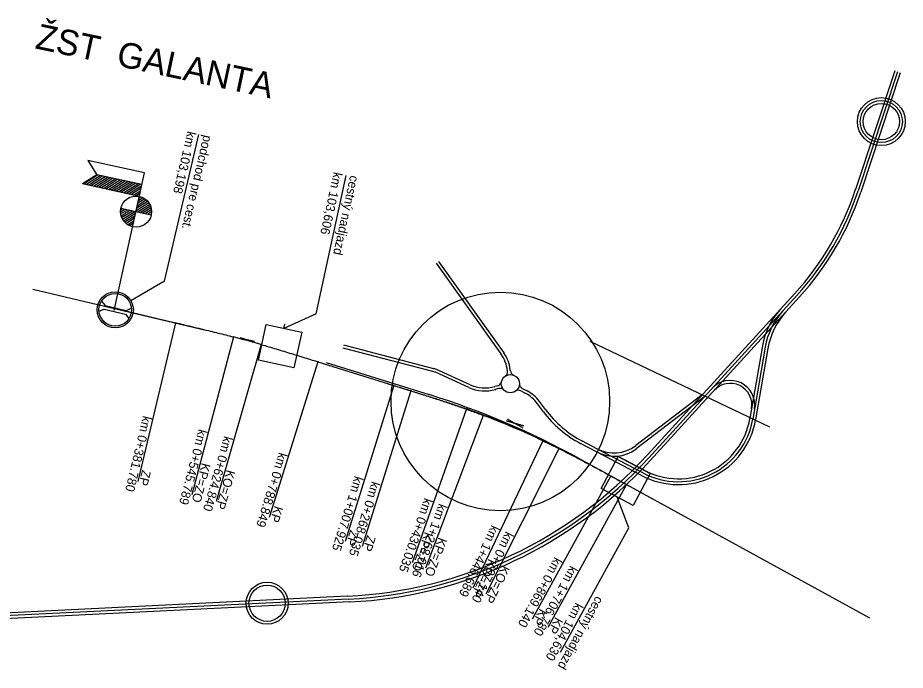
# Model space of a CAD drawing. Extents: x -566241 to -446826, y -1330151 to -1274078.
# Drawn here: x -528029 to -525582, y -1281724 to -1279926 of the extents above; entities that cross this region are included whole.
import ezdxf

# ---------------------------------------------------------------- set-up
doc = ezdxf.new("R2010")
doc.units = 0
for name, color, linetype in [('1-POPIS', 7, 'Continuous'), ('10_cesty_plochy', 7, 'Continuous'), ('os', 7, 'Continuous'), ('os hl bod', 7, 'Continuous'), ('Posúdenie 200km Bloss', 7, 'Continuous'), ('Posúdenie_200km', 7, 'Continuous'), ('sit_stanicenie', 7, 'Continuous'), ('STANICE', 7, 'Continuous'), ('stanicenie', 7, 'Continuous')]:
    doc.layers.add(name, color=color, linetype=linetype)

msp = doc.modelspace()

# ---------------------------------------------------------------- linework, layer by layer
at = {"layer": '1-POPIS'}
for p, q in [((-527624.7, -1280652), (-527530, -1280247.6)), ((-527206.8, -1280742.2), (-527123.8, -1280360.7)), ((-527624.7, -1280652), (-527717.3, -1280705.9)), ((-527798.4, -1280706.8), (-527788.5, -1280719.4)), ((-527790.8, -1280729.1), (-527805.2, -1280736)), ((-527790.8, -1280729.1), (-527732.4, -1280742.8)), ((-527788.5, -1280719.4), (-527730.1, -1280733.1)), ((-527730.1, -1280733.1), (-527715.7, -1280726.2)), ((-527732.4, -1280742.8), (-527722.6, -1280755.4)), ((-527206.8, -1280742.2), (-527295.2, -1280782.3)), ((-527295.2, -1280782.3), (-527292.7, -1280770.8)), ((-526344.7, -1281332.4), (-526376.8, -1281247)), ((-526532.6, -1281674.7), (-526344.7, -1281332.4))]:
    msp.add_line(p, q, dxfattribs=at)
for points in [[(-527344, -1280771.7), (-527246.3, -1280793), (-527267.6, -1280890.7), (-527365.3, -1280869.4)], [(-526373.7, -1281135.2), (-526285.5, -1281182.5), (-526332.8, -1281270.6), (-526420.9, -1281223.4)]]:
    msp.add_lwpolyline(points, close=True, dxfattribs=at)
for radius in [50, 45]:
    msp.add_circle((-527760.5, -1280731.1), radius, dxfattribs=at)
at = {"layer": '10_cesty_plochy'}
for p, q in [((-525611.3, -1280072.7), (-525719.1, -1280399)), ((-525603.7, -1280075.2), (-525712.1, -1280403.1)), ((-525596.1, -1280077.8), (-525705, -1280407.2)), ((-526875.2, -1280602.6), (-526697, -1280852.2)), ((-526868.7, -1280598), (-526689.3, -1280849.3)), ((-527988.1, -1280673.9), (-527510.4, -1280787)), ((-526293.3, -1281131.2), (-525887.9, -1280687.3)), ((-526289.6, -1281139), (-525880.9, -1280691.5)), ((-526285.9, -1281146.8), (-525873.8, -1280695.6)), ((-527133.2, -1280835.7), (-526885.6, -1280900.5)), ((-527131.2, -1280828), (-526882.9, -1280893)), ((-526452.2, -1280817.4), (-525956, -1281053.7)), ((-525975.9, -1280830.5), (-526010.4, -1281030.8)), ((-525968.4, -1280834.1), (-526002.5, -1281032.2)), ((-525960.9, -1280837.8), (-525994.6, -1281033.5)), ((-527179.2, -1280876.1), (-526950.9, -1280947.3)), ((-527179.2, -1280876.1), (-526895.2, -1280964.7)), ((-526785.5, -1280944.9), (-526877.7, -1280903.3)), ((-526782.2, -1280937.7), (-526875, -1280895.8)), ((-526679, -1280900.1), (-526679.1, -1280899.1)), ((-526671, -1280899.2), (-526671.4, -1280896.1)), ((-526703.8, -1280948.2), (-526713.8, -1280951)), ((-526706, -1280940.5), (-526713.6, -1280942.7)), ((-526641.7, -1280954.6), (-526629.9, -1280960.8)), ((-526638, -1280947.5), (-526624.6, -1280954.6)), ((-526574.5, -1281005.6), (-526590.8, -1280983.6)), ((-526142.5, -1280965.4), (-526325, -1281104.9)), ((-526137.6, -1280971.8), (-526324.2, -1281114.4)), ((-526579.8, -1281011.9), (-526596.1, -1280989.8)), ((-526431.3, -1281123.5), (-526477.8, -1281099.2)), ((-526432.1, -1281114.1), (-526472.5, -1281092.9)), ((-526304, -1281181.2), (-526432.1, -1281114.1)), ((-526307.7, -1281188.3), (-526431.3, -1281123.5)), ((-526482.7, -1281140.2), (-525681.1, -1281580.3)), ((-526300.3, -1281174.1), (-526375.8, -1281134.5)), ((-527120.7, -1281520.5), (-528089.6, -1281568)), ((-527113.3, -1281536.2), (-528094.5, -1281584.2)), ((-527117, -1281528.3), (-528092, -1281576.1))]:
    msp.add_line(p, q, dxfattribs=at)
for centre, radius in [((-525648.1, -1280212.3), 66), ((-525648.1, -1280212.3), 58), ((-525648.1, -1280212.3), 50), ((-526698.6, -1280983.6), 301.3), ((-526671, -1280934.7), 25), ((-527341.7, -1281539.9), 58), ((-527341.7, -1281539.9), 50)]:
    msp.add_circle(centre, radius, dxfattribs=at)
for centre, radius, start, end in [((-526478.7, -1280147.8), 800, 317.5966, 341.7049), ((-526471.6, -1280152), 800, 317.5966, 341.7049), ((-526464.6, -1280156.1), 800, 317.5966, 341.7049), ((-525778.8, -1280864.4), 200, 137.5966, 170.2357), ((-525771.3, -1280868.1), 200, 137.5966, 170.2357), ((-525763.8, -1280871.7), 200, 137.5966, 170.2357), ((-526778.4, -1280910.3), 100, 6.4527, 35.5191), ((-526770.7, -1280907.4), 100, 6.4527, 35.5191), ((-526898.3, -1280948.9), 50, 65.7033, 75.323), ((-526895.6, -1280941.3), 50, 65.7033, 75.323), ((-526693.9, -1280901.8), 15, 304.812, 6.4527), ((-526656.1, -1280897.5), 15, 186.4527, 248.0933), ((-526710.1, -1280926.1), 15, 285.9428, 347.5834), ((-526631, -1280934.2), 15, 180.5894, 242.23), ((-526064.9, -1280993.8), 68, 350.2357, 137.5966), ((-526064.9, -1280993.8), 60, 350.2357, 137.5966), ((-526741.1, -1280846.5), 108, 245.7033, 285.9428), ((-526741.1, -1280846.5), 100, 245.7033, 285.9428), ((-526699.7, -1280962.6), 15, 44.3021, 105.9428), ((-526648.7, -1280967.9), 15, 62.23, 123.8707), ((-526671.2, -1281043.1), 100, 36.5095, 62.23), ((-527565.5, -1283112.6), 2250, 61.2335, 72.6695), ((-526676.5, -1281049.3), 100, 36.5095, 62.23), ((-526333.3, -1280827.1), 300, 216.5095, 242.3626), ((-526338.7, -1280833.4), 300, 216.5095, 242.3626), ((-526207.5, -1280996.9), 216, 242.3626, 350.2357), ((-526207.5, -1280996.9), 208, 242.3626, 350.2357), ((-526207.5, -1280996.9), 200, 242.3626, 350.2357), ((-526385.7, -1281025.5), 100, 242.3626, 307.4004), ((-527179.4, -1280321.9), 1200, 272.8042, 317.5966), ((-526384.9, -1281034.9), 100, 242.3626, 307.4004), ((-527175.7, -1280329.8), 1200, 272.8042, 317.5966), ((-527172, -1280337.6), 1200, 272.8042, 317.5966)]:
    msp.add_arc(centre, radius, start, end, dxfattribs=at)
at = {"layer": 'os'}
for p, q in [((-527010.6, -1280933.9), (-526945.7, -1280954.2)), ((-526393.9, -1281189), (-526279.2, -1281251.9))]:
    msp.add_line(p, q, dxfattribs=at)
for points in [[(-526945.7, -1280954.2), (-526941.6, -1280955.5), (-526937.6, -1280956.7), (-526933.5, -1280958), (-526929.4, -1280959.3), (-526925.3, -1280960.5), (-526921.3, -1280961.8), (-526917.2, -1280963.1), (-526913.1, -1280964.4), (-526909.1, -1280965.6), (-526905, -1280966.9), (-526900.9, -1280968.2), (-526896.9, -1280969.5), (-526892.8, -1280970.7), (-526888.7, -1280972), (-526884.7, -1280973.3), (-526880.6, -1280974.6), (-526876.5, -1280975.9), (-526872.5, -1280977.2), (-526868.4, -1280978.5), (-526864.4, -1280979.8), (-526860.3, -1280981.1), (-526856.2, -1280982.4), (-526852.2, -1280983.7), (-526848.1, -1280985), (-526844.1, -1280986.3), (-526840, -1280987.7), (-526836, -1280989), (-526831.9, -1280990.3), (-526827.9, -1280991.7), (-526823.8, -1280993), (-526819.8, -1280994.4), (-526815.8, -1280995.8), (-526811.7, -1280997.2), (-526807.7, -1280998.5), (-526803.7, -1280999.9), (-526799.6, -1281001.3), (-526795.6, -1281002.7), (-526791.6, -1281004.2)], [(-526536.8, -1281112.6), (-526533, -1281114.5), (-526529.2, -1281116.4), (-526525.4, -1281118.3), (-526521.6, -1281120.3), (-526517.8, -1281122.2), (-526514, -1281124.2), (-526510.2, -1281126.1), (-526506.4, -1281128.1), (-526502.6, -1281130.1), (-526498.9, -1281132.1), (-526495.1, -1281134), (-526491.3, -1281136), (-526487.6, -1281138), (-526483.8, -1281140), (-526480, -1281142), (-526476.3, -1281144), (-526472.5, -1281146.1), (-526468.8, -1281148.1), (-526465, -1281150.1), (-526461.3, -1281152.1), (-526457.5, -1281154.2), (-526453.8, -1281156.2), (-526450, -1281158.2), (-526446.3, -1281160.3), (-526442.5, -1281162.3), (-526438.8, -1281164.4), (-526435.1, -1281166.4), (-526431.3, -1281168.5), (-526427.6, -1281170.5), (-526423.8, -1281172.5), (-526420.1, -1281174.6), (-526416.4, -1281176.6), (-526412.6, -1281178.7), (-526408.9, -1281180.7), (-526405.1, -1281182.8), (-526401.4, -1281184.9), (-526397.7, -1281186.9), (-526393.9, -1281189)]]:
    msp.add_lwpolyline(points, dxfattribs=at)
msp.add_arc((-527523.8, -1283078.7), 2200, 63.343, 70.5598, dxfattribs=at)
at = {"layer": 'os hl bod'}
for centre in [(-526945.7, -1280954.2), (-526791.6, -1281004.2), (-526536.8, -1281112.6), (-526393.9, -1281189)]:
    msp.add_circle(centre, 0.75, dxfattribs=at)
at = {"layer": 'Posúdenie 200km Bloss'}
for p, q in [((-526680, -1281031.9), (-526636.2, -1281055.9)), ((-526634.7, -1281051.2), (-526681.6, -1281036.6))]:
    msp.add_line(p, q, dxfattribs=at)
at = {"layer": 'Posúdenie_200km'}
for p, q in [((-527762.1, -1280726.8), (-527594, -1280766.7)), ((-527376.7, -1280818.3), (-527416.1, -1280808.9)), ((-527415.6, -1280807.6), (-527377.1, -1280819.6)), ((-527201.6, -1280874.4), (-526992.4, -1280939.6)), ((-526680, -1281031.9), (-526636.2, -1281055.9)), ((-526681.6, -1281036.6), (-526634.7, -1281051.2)), ((-526351, -1281212.5), (-526181.5, -1281305.5))]:
    msp.add_line(p, q, dxfattribs=at)
for points in [[(-527673.6, -1280747.8), (-527673.8, -1280748.8)], [(-527594, -1280766.7), (-527697.9, -1281204.5)], [(-527594, -1280766.7), (-527588.7, -1280768), (-527583.4, -1280769.2), (-527578, -1280770.5), (-527572.7, -1280771.7), (-527567.4, -1280773), (-527562.1, -1280774.3), (-527556.8, -1280775.5), (-527551.5, -1280776.8), (-527546.1, -1280778.1), (-527540.8, -1280779.4), (-527535.5, -1280780.6), (-527530.2, -1280781.9), (-527524.9, -1280783.2), (-527519.6, -1280784.5), (-527514.3, -1280785.8), (-527508.9, -1280787.1), (-527503.6, -1280788.4), (-527498.3, -1280789.7), (-527493, -1280791), (-527487.7, -1280792.3), (-527482.4, -1280793.6), (-527477.1, -1280795), (-527471.8, -1280796.3), (-527466.5, -1280797.6), (-527461.2, -1280799), (-527455.9, -1280800.3), (-527450.6, -1280801.7), (-527445.3, -1280803), (-527440, -1280804.4), (-527434.7, -1280805.8)], [(-527576.3, -1280770.9), (-527576.5, -1280771.9)], [(-527434.7, -1280805.8), (-527548.9, -1281241.1)], [(-527479.1, -1280794.5), (-527479.3, -1280795.4)], [(-527358.5, -1280826.7), (-527482.4, -1281259.3)], [(-527382.4, -1280820), (-527382.7, -1280820.9)], [(-527358.5, -1280826.7), (-527353.2, -1280828.2), (-527348, -1280829.7), (-527342.7, -1280831.3), (-527337.5, -1280832.8), (-527332.2, -1280834.3), (-527327, -1280835.9), (-527321.8, -1280837.4), (-527316.5, -1280839), (-527311.3, -1280840.6), (-527306, -1280842.1), (-527300.8, -1280843.7), (-527295.6, -1280845.3), (-527290.3, -1280846.9), (-527285.1, -1280848.5), (-527279.9, -1280850.1), (-527274.7, -1280851.7), (-527269.4, -1280853.3), (-527264.2, -1280854.9), (-527259, -1280856.5), (-527253.8, -1280858.1), (-527248.5, -1280859.7), (-527243.3, -1280861.3), (-527238.1, -1280863), (-527232.9, -1280864.6), (-527227.7, -1280866.2), (-527222.4, -1280867.8), (-527217.2, -1280869.5), (-527212, -1280871.1), (-527206.8, -1280872.7), (-527201.6, -1280874.4)], [(-527286.4, -1280848.1), (-527286.7, -1280849)], [(-527201.6, -1280874.4), (-527335.6, -1281303.9)], [(-527190.9, -1280877.7), (-527191.2, -1280878.6)], [(-527095.5, -1280907.5), (-527095.8, -1280908.4)], [(-526992.4, -1280939.6), (-527126.5, -1281369.2)], [(-527000, -1280937.2), (-527000.3, -1280938.2)], [(-526992.4, -1280939.6), (-526988.4, -1280940.9), (-526984.3, -1280942.2), (-526980.2, -1280943.4), (-526976.2, -1280944.7), (-526972.1, -1280946), (-526968, -1280947.2), (-526963.9, -1280948.5), (-526959.9, -1280949.8), (-526955.8, -1280951.1), (-526951.7, -1280952.3), (-526947.7, -1280953.6), (-526943.6, -1280954.9), (-526939.5, -1280956.2), (-526935.5, -1280957.5), (-526931.4, -1280958.7), (-526927.3, -1280960), (-526923.3, -1280961.3), (-526919.2, -1280962.6), (-526915.1, -1280963.9), (-526911.1, -1280965.2), (-526907, -1280966.5), (-526903, -1280967.8), (-526898.9, -1280969.1), (-526894.8, -1280970.4), (-526890.8, -1280971.7), (-526886.7, -1280973), (-526882.7, -1280974.3), (-526878.6, -1280975.6), (-526874.6, -1280977), (-526870.5, -1280978.3), (-526866.5, -1280979.6), (-526862.4, -1280981), (-526858.4, -1280982.3), (-526854.3, -1280983.6), (-526850.3, -1280985), (-526846.2, -1280986.3), (-526842.2, -1280987.7), (-526838.1, -1280989.1), (-526834.1, -1280990.4), (-526830.1, -1280991.8), (-526826, -1280993.2), (-526822, -1280994.6), (-526818, -1280995.9), (-526813.9, -1280997.3), (-526809.9, -1280998.7), (-526805.9, -1281000.1), (-526801.9, -1281001.5), (-526797.8, -1281003), (-526793.8, -1281004.4), (-526789.8, -1281005.8), (-526785.8, -1281007.2), (-526781.8, -1281008.7), (-526777.8, -1281010.1), (-526773.7, -1281011.6), (-526769.7, -1281013), (-526765.7, -1281014.5), (-526761.7, -1281016), (-526757.7, -1281017.5), (-526753.7, -1281019), (-526749.8, -1281020.5), (-526745.8, -1281022)], [(-526904.6, -1280967.3), (-526904.9, -1280968.2)], [(-526809.7, -1280998.8), (-526810, -1280999.7)], [(-526745.8, -1281022), (-526905, -1281442.9)], [(-526715.9, -1281033.5), (-526716.3, -1281034.4)], [(-526623.8, -1281072.3), (-526624.2, -1281073.2)], [(-526581.4, -1281091.9), (-526774.2, -1281498.5)], [(-526581.4, -1281091.9), (-526577.5, -1281093.7), (-526573.7, -1281095.5), (-526569.9, -1281097.4), (-526566, -1281099.2), (-526562.2, -1281101.1), (-526558.3, -1281103), (-526554.5, -1281104.8), (-526550.7, -1281106.7), (-526546.9, -1281108.6), (-526543, -1281110.5), (-526539.2, -1281112.4), (-526535.4, -1281114.3), (-526531.6, -1281116.2), (-526527.8, -1281118.1), (-526524, -1281120.1), (-526520.2, -1281122), (-526516.4, -1281123.9), (-526512.6, -1281125.8), (-526508.8, -1281127.8), (-526505, -1281129.7), (-526501.2, -1281131.7), (-526497.4, -1281133.7), (-526493.6, -1281135.6), (-526489.8, -1281137.6), (-526486.1, -1281139.6), (-526482.3, -1281141.5), (-526478.5, -1281143.5), (-526474.7, -1281145.5), (-526471, -1281147.5), (-526467.2, -1281149.5), (-526463.4, -1281151.5), (-526459.7, -1281153.5), (-526455.9, -1281155.5), (-526452.1, -1281157.5), (-526448.4, -1281159.5), (-526444.6, -1281161.5), (-526440.9, -1281163.5), (-526437.1, -1281165.5), (-526433.3, -1281167.6), (-526429.6, -1281169.6), (-526425.8, -1281171.6), (-526422.1, -1281173.6), (-526418.3, -1281175.7), (-526414.6, -1281177.7), (-526410.8, -1281179.7), (-526407.1, -1281181.8), (-526403.4, -1281183.8), (-526399.6, -1281185.9), (-526395.9, -1281187.9), (-526392.1, -1281189.9), (-526388.4, -1281192), (-526384.6, -1281194), (-526380.9, -1281196.1), (-526377.2, -1281198.1), (-526373.4, -1281200.2), (-526369.7, -1281202.2), (-526365.9, -1281204.3), (-526362.2, -1281206.3), (-526358.5, -1281208.4), (-526354.7, -1281210.4), (-526351, -1281212.5)], [(-526533.5, -1281115.3), (-526533.9, -1281116.2)], [(-526444.8, -1281161.4), (-526445.2, -1281162.3)], [(-526351, -1281212.5), (-526567.5, -1281607)], [(-526356.9, -1281209.2), (-526357.4, -1281210.1)], [(-526269.3, -1281257.3), (-526269.8, -1281258.2)], [(-526181.6, -1281305.4), (-526182.1, -1281306.3)]]:
    msp.add_lwpolyline(points, dxfattribs=at)
for centre in [(-527594, -1280766.7), (-527434.7, -1280805.8), (-527358.5, -1280826.7), (-527201.6, -1280874.4), (-526992.4, -1280939.6), (-526745.8, -1281022), (-526581.4, -1281091.9), (-526351, -1281212.5)]:
    msp.add_circle(centre, 0.75, dxfattribs=at)
for centre, radius, start, end in [((-528322.5, -1284191.3), 3500, 74.0118, 75.3059), ((-527524.1, -1283079.7), 2200, 64.6284, 69.2817)]:
    msp.add_arc(centre, radius, start, end, dxfattribs=at)
at = {"layer": 'sit_stanicenie'}
for points in [[(-527010.6, -1280933.9), (-527010.9, -1280934.9)], [(-526915.2, -1280963.7), (-526915.5, -1280964.7)], [(-526820, -1280994.3), (-526820.3, -1280995.3)], [(-526726, -1281028.5), (-526726.4, -1281029.4)], [(-526633.7, -1281066.9), (-526634.1, -1281067.8)], [(-526543.2, -1281109.4), (-526543.6, -1281110.3)], [(-526454.6, -1281155.8), (-526455.1, -1281156.6)], [(-526366.9, -1281203.8), (-526367.4, -1281204.7)], [(-526279.2, -1281251.9), (-526279.7, -1281252.8)]]:
    msp.add_lwpolyline(points, dxfattribs=at)
at = {"layer": 'STANICE'}
for p, q in [((-527836.5, -1280319.2), (-527811.4, -1280358.6)), ((-527679.6, -1280353.9), (-527836.5, -1280319.2)), ((-527811.4, -1280358.6), (-527850.7, -1280383.7)), ((-527848.4, -1280384.2), (-527809, -1280359.1)), ((-527841.5, -1280385.7), (-527802.1, -1280360.6)), ((-527834.6, -1280387.2), (-527795.2, -1280362.1)), ((-527827.7, -1280388.8), (-527788.3, -1280363.7)), ((-527820.8, -1280390.3), (-527781.4, -1280365.2)), ((-527813.9, -1280391.8), (-527774.5, -1280366.7)), ((-527686.7, -1280386.1), (-527811.4, -1280358.6)), ((-527806.9, -1280393.4), (-527767.6, -1280368.2)), ((-527800, -1280394.9), (-527760.7, -1280369.8)), ((-527793.1, -1280396.4), (-527753.8, -1280371.3)), ((-527786.2, -1280397.9), (-527746.9, -1280372.8)), ((-527763.5, -1280733.2), (-527679.6, -1280353.9)), ((-527693.8, -1280418.4), (-527850.7, -1280383.7)), ((-527779.3, -1280399.5), (-527740, -1280374.4)), ((-527772.4, -1280401), (-527733.1, -1280375.9)), ((-527765.5, -1280402.5), (-527726.2, -1280377.4)), ((-527758.6, -1280404), (-527719.3, -1280378.9)), ((-527751.7, -1280405.6), (-527712.3, -1280380.5)), ((-527744.8, -1280407.1), (-527705.4, -1280382)), ((-527737.9, -1280408.6), (-527698.5, -1280383.5)), ((-527731, -1280410.2), (-527691.6, -1280385)), ((-527724.1, -1280411.7), (-527687.2, -1280388.1)), ((-527717.2, -1280413.2), (-527688.7, -1280395)), ((-527710.3, -1280414.7), (-527690.2, -1280401.9)), ((-527710.3, -1280414.7), (-527690.2, -1280401.9)), ((-527703.4, -1280416.3), (-527691.7, -1280408.8)), ((-527703.4, -1280416.3), (-527691.7, -1280408.8)), ((-527696.5, -1280417.8), (-527693.3, -1280415.7)), ((-527696.5, -1280417.8), (-527693.3, -1280415.7)), ((-527696.3, -1280429.5), (-527684.1, -1280421.8)), ((-527694.8, -1280422.6), (-527689.8, -1280419.5)), ((-527702.4, -1280457.2), (-527668.2, -1280435.3)), ((-527700.9, -1280450.3), (-527671.3, -1280431.4)), ((-527699.4, -1280443.4), (-527675, -1280427.8)), ((-527699.4, -1280461.2), (-527665.5, -1280439.5)), ((-527697.8, -1280436.4), (-527679.3, -1280424.6)), ((-527692.5, -1280462.7), (-527663.3, -1280444.1)), ((-527746.1, -1280461.3), (-527734, -1280453.6)), ((-527745.8, -1280455.2), (-527740.9, -1280452)), ((-527745.7, -1280466.9), (-527727.1, -1280455.1)), ((-527745.1, -1280451.1), (-527661.1, -1280469.7)), ((-527744.5, -1280472.1), (-527720.2, -1280456.6)), ((-527742.8, -1280477), (-527713.3, -1280458.1)), ((-527740.6, -1280481.5), (-527706.4, -1280459.7)), ((-527737.9, -1280485.7), (-527704, -1280464.1)), ((-527734.7, -1280489.6), (-527705.5, -1280471)), ((-527685.6, -1280464.2), (-527661.7, -1280449)), ((-527678.7, -1280465.8), (-527660.6, -1280454.2)), ((-527671.8, -1280467.3), (-527660.1, -1280459.8)), ((-527731, -1280493.2), (-527707, -1280477.9)), ((-527726.7, -1280496.4), (-527708.5, -1280484.8)), ((-527721.8, -1280499.1), (-527710.1, -1280491.7))]:
    msp.add_line(p, q, dxfattribs=at)
msp.add_circle((-527703.1, -1280460.4), 43, dxfattribs=at)
at = {"layer": 'stanicenie'}
for points in [[(-526945.7, -1280954.2), (-527079.7, -1281383.8)], [(-526791.6, -1281004.2), (-526941.4, -1281428.5)], [(-526536.8, -1281112.6), (-526738.7, -1281514.7)], [(-526393.9, -1281189), (-526610.5, -1281583.4)]]:
    msp.add_lwpolyline(points, dxfattribs=at)

# ---------------------------------------------------------------- texts
at = {"layer": '1-POPIS'}
for s, rotation, p in [('km 103,198', 256.82, (-527561.2, -1280237.3)), ('podchod pre cest.', 256.82, (-527516.9, -1280247.8)), ('km 103,606', 257.7335, (-527158, -1280350)), ('cestný nadjazd', 257.7335, (-527112.3, -1280359.3)), ('cestný nadjazd', 241.2437, (-526434.4, -1281518.3)), ('km 104,630', 241.2437, (-526490.7, -1281536.5))]:
    msp.add_text(s, height=25, rotation=rotation, dxfattribs=at).set_placement(p)
at = {"layer": 'Posúdenie_200km'}
for s, rotation, p in [('km 0+381.780', 256.6484, (-527684, -1281021.8)), ('km 0+545.789', 255.3059, (-527530.7, -1281058.7)), ('km 0+624.840', 254.0118, (-527460.2, -1281077.5)), ('km 0+788.849', 252.6693, (-527309, -1281122.5)), ('KP=ZO  ', 255.3059, (-527521.6, -1281151.6)), ('ZP ', 256.6484, (-527686.2, -1281171)), ('KO=ZP', 254.0118, (-527453.2, -1281170.5)), ('km 1+007.925', 252.6693, (-527099.9, -1281187.7)), ('KP ', 252.6693, (-527321.1, -1281269.8)), ('km 1+268.016', 249.2817, (-526867.8, -1281263.4)), ('km 1+446.689', 244.6284, (-526722.5, -1281322.6)), ('ZP ', 252.6693, (-527112.4, -1281336.6)), ('KP=ZO  ', 249.2817, (-526868.5, -1281356.7)), ('KO=ZP', 244.6284, (-526730.9, -1281415.6)), ('km 1+706.780', 241.2408, (-526505.6, -1281434.5)), ('KP ', 241.2408, (-526546.5, -1281576.4))]:
    msp.add_text(s, height=25, rotation=rotation, dxfattribs=at).set_placement(p)
at = {"layer": 'STANICE'}
msp.add_text('ŽST  GALANTA', height=70, rotation=347.9806, dxfattribs=at).set_placement((-527983.8, -1280010.1))
at = {"layer": 'stanicenie'}
for s, rotation, p in [('km 0+268.035', 252.6693, (-527053.2, -1281202.3)), ('km 0+430.035', 250.5598, (-526908.1, -1281248.1)), ('KP=ZO  ', 250.5598, (-526906.8, -1281341.6)), ('km 0+707.140', 243.343, (-526683.1, -1281340.2)), ('ZP ', 252.6693, (-527065.7, -1281351.1)), ('km 0+869.140', 241.2335, (-526548.6, -1281411)), ('KO=ZP', 243.343, (-526693.5, -1281432.9)), ('KP ', 241.2335, (-526589.5, -1281552.8))]:
    msp.add_text(s, height=25, rotation=rotation, dxfattribs=at).set_placement(p)

doc.saveas('drawing.dxf')
